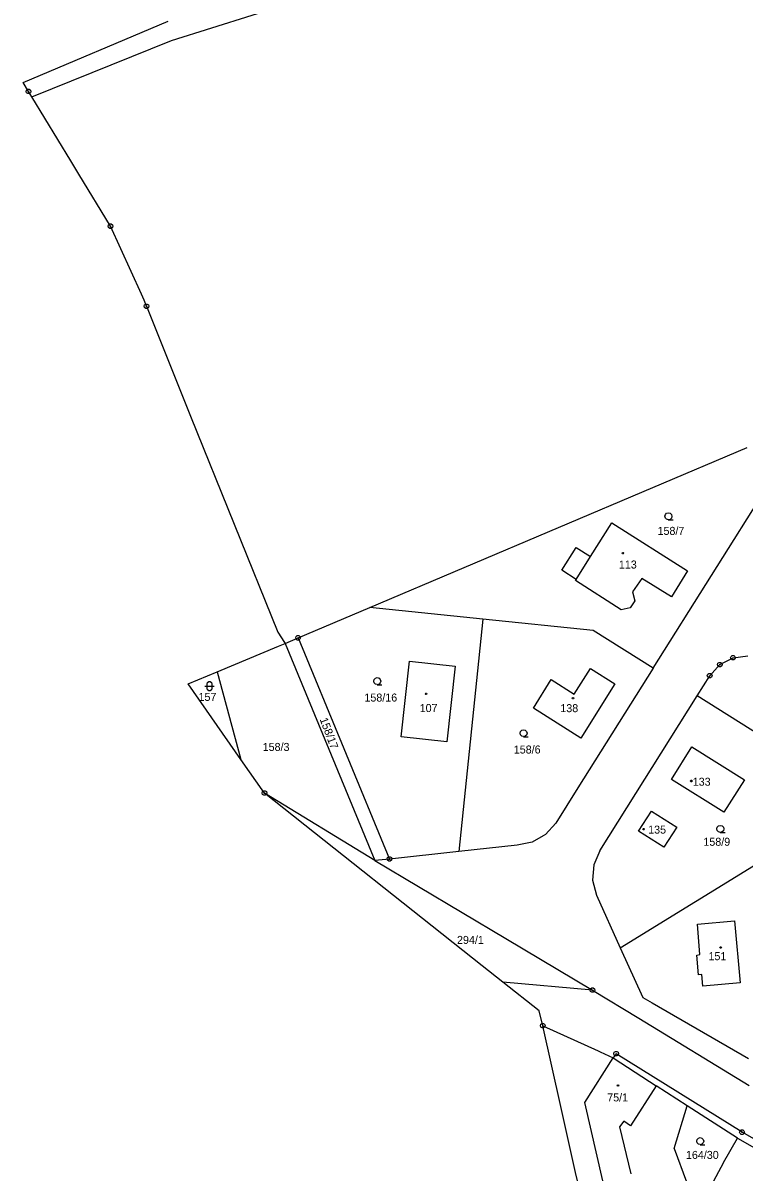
# Model space of a CAD drawing. Extents: x -780000 to -777378, y -1011169 to -1009297.
# Drawn here: x -779564.1 to -779410.9, y -1010124.6 to -1009880.5 of the extents above; entities that cross this region are included whole.
import ezdxf

# ---------------------------------------------------------------- set-up
doc = ezdxf.new("R2010")
doc.units = 0
for name, color, linetype in [('Default', 7, 'Continuous'), ('KN_HRANICE', 7, 'Continuous'), ('KN_KULTURY', 7, 'Continuous'), ('KN_PARCELY', 7, 'Continuous'), ('KN_SLUCKY', 7, 'Continuous')]:
    doc.layers.add(name, color=color, linetype=linetype)

# ---------------------------------------------------------------- blocks, each defined once
blk = doc.blocks.new('304')
at = {"layer": 'Default'}
blk.add_lwpolyline([(0, 0), (-0.38, 0.1), (-0.65, 0.37), (-0.75, 0.74), (-0.65, 1.11), (-0.38, 1.38), (-0.01, 1.48), (0.36, 1.38), (0.63, 1.11), (0.73, 0.73), (0.63, 0.35), (0.36, 0.08), (-0.02, -0.02), (0.98, -0.02)], dxfattribs=at)
blk = doc.blocks.new('316')
at = {"layer": 'Default'}
for points in [[(-1, 1), (0.27, 1), (1, 1)], [(-0.5, 1.5), (-0.4, 1.79), (-0.15, 1.97), (0.16, 1.97), (0.41, 1.79), (0.51, 1.5), (0.51, 0.5), (0.41, 0.21), (0.16, 0.03), (-0.15, 0.03), (-0.4, 0.21), (-0.5, 0.5), (-0.5, 1.5)]]:
    blk.add_lwpolyline(points, dxfattribs=at)
blk = doc.blocks.new('105')
at = {"layer": 'Default'}
blk.add_line((-0.12, 0), (0.12, 0), dxfattribs=at)
blk.add_lwpolyline([(0.15, 0.48), (0.4, 0.3), (0.5, 0.01), (0.4, -0.28), (0.15, -0.46), (-0.16, -0.46), (-0.41, -0.28), (-0.51, 0.01), (-0.41, 0.3), (-0.16, 0.48), (0.15, 0.48)], dxfattribs=at)
blk = doc.blocks.new('402')
at = {"layer": 'Default'}
blk.add_lwpolyline([(0.09, 0.15), (0.18, 0), (0.09, -0.15), (-0.09, -0.15), (-0.18, 0), (-0.09, 0.15), (0.09, 0.15)], dxfattribs=at)

msp = doc.modelspace()

# ---------------------------------------------------------------- linework, layer by layer
at = {"layer": 'KN_HRANICE'}
for p, q in [((-779532.56, -1009884.15), (-779506.87, -1009876.1)), ((-779564.1, -1009893.09), (-779533.32, -1009880.08)), ((-779562.25, -1009896.12), (-779532.56, -1009884.15)), ((-779562.94, -1009894.99), (-779564.1, -1009893.09)), ((-779562.25, -1009896.12), (-779562.94, -1009894.99)), ((-779553.96, -1009909.75), (-779562.25, -1009896.12)), ((-779552.25, -1009912.56), (-779553.96, -1009909.75)), ((-779545.52, -1009923.61), (-779552.25, -1009912.56)), ((-779538.94, -1009938.03), (-779545.52, -1009923.61)), ((-779538.37, -1009939.28), (-779538.94, -1009938.03)), ((-779537.89, -1009940.61), (-779538.37, -1009939.28)), ((-779537.89, -1009940.61), (-779528.57, -1009963.94)), ((-779528.57, -1009963.94), (-779510, -1010009.82)), ((-779490.5, -1010004.56), (-779410.38, -1009970.58)), ((-779430.36, -1010017.45), (-779405.63, -1009978.11)), ((-779443.63, -1009993.74), (-779439.14, -1009986.62)), ((-779439.14, -1009986.62), (-779423.07, -1009996.75)), ((-779449.77, -1009996.67), (-779446.72, -1009991.8)), ((-779446.72, -1009991.8), (-779443.63, -1009993.74)), ((-779446.7, -1009998.61), (-779449.77, -1009996.67)), ((-779423.07, -1009996.75), (-779426.49, -1010002.32)), ((-779446.86, -1009998.86), (-779446.7, -1009998.61)), ((-779437.12, -1010005.06), (-779446.86, -1009998.86)), ((-779432.77, -1009998.38), (-779434.71, -1010001.23)), ((-779426.49, -1010002.32), (-779432.77, -1009998.38)), ((-779434.71, -1010001.23), (-779434.23, -1010003.15)), ((-779434.23, -1010003.15), (-779435.26, -1010004.63)), ((-779505.72, -1010011.01), (-779490.5, -1010004.56)), ((-779466.49, -1010007.04), (-779490.5, -1010004.56)), ((-779435.26, -1010004.63), (-779437.12, -1010005.06)), ((-779466.49, -1010007.04), (-779471.6, -1010056.37)), ((-779443.07, -1010009.46), (-779466.49, -1010007.04)), ((-779510, -1010009.82), (-779508.57, -1010011.97)), ((-779508.48, -1010012.18), (-779505.72, -1010011.01)), ((-779505.72, -1010011.01), (-779486.32, -1010057.97)), ((-779430.36, -1010017.45), (-779443.07, -1010009.46)), ((-779522.9, -1010018.23), (-779509.9, -1010012.78)), ((-779509.9, -1010012.78), (-779508.48, -1010012.18)), ((-779508.57, -1010011.97), (-779508.48, -1010012.18)), ((-779508.48, -1010012.18), (-779489.42, -1010058.31)), ((-779483.83, -1010032.01), (-779482.07, -1010015.94)), ((-779482.07, -1010015.94), (-779472.39, -1010016.99)), ((-779416.21, -1010016.69), (-779413.4, -1010015.24)), ((-779413.4, -1010015.24), (-779410.26, -1010014.85)), ((-779529.07, -1010020.81), (-779522.9, -1010018.23)), ((-779522.9, -1010018.23), (-779517.85, -1010036.84)), ((-779472.39, -1010016.99), (-779474.14, -1010033.11)), ((-779447.1, -1010022.98), (-779443.68, -1010017.51)), ((-779443.68, -1010017.51), (-779438.46, -1010020.79)), ((-779418.36, -1010019.05), (-779416.21, -1010016.69)), ((-779517.85, -1010036.84), (-779529.07, -1010020.81)), ((-779455.79, -1010025.95), (-779452.01, -1010019.89)), ((-779452.01, -1010019.89), (-779447.1, -1010022.98)), ((-779438.46, -1010020.79), (-779445.71, -1010032.28)), ((-779421.04, -1010023.31), (-779418.36, -1010019.05)), ((-779441.71, -1010056.21), (-779421.04, -1010023.31)), ((-779402.59, -1010034.91), (-779421.04, -1010023.31)), ((-779445.71, -1010032.28), (-779455.79, -1010025.95)), ((-779474.14, -1010033.11), (-779483.83, -1010032.01)), ((-779512.85, -1010043.97), (-779517.85, -1010036.84)), ((-779489.42, -1010058.31), (-779512.85, -1010043.97)), ((-779466.67, -1010080.62), (-779512.85, -1010043.97)), ((-779451.04, -1010050.34), (-779453.2, -1010052.79)), ((-779437.34, -1010076.8), (-779393.43, -1010049.78)), ((-779459.24, -1010055.03), (-779471.6, -1010056.37)), ((-779456.04, -1010054.41), (-779459.24, -1010055.03)), ((-779471.6, -1010056.37), (-779486.32, -1010057.97)), ((-779441.71, -1010056.21), (-779442.97, -1010059.22)), ((-779486.32, -1010057.97), (-779489.42, -1010058.31)), ((-779489.42, -1010058.31), (-779461.6, -1010074.87)), ((-779442.97, -1010059.22), (-779443.2, -1010062.48)), ((-779443.2, -1010062.48), (-779442.37, -1010065.63)), ((-779442.37, -1010065.63), (-779437.34, -1010076.8)), ((-779420.98, -1010071.8), (-779413.13, -1010071.11)), ((-779420.44, -1010078.28), (-779420.98, -1010071.8)), ((-779413.13, -1010071.11), (-779411.92, -1010084.25)), ((-779461.6, -1010074.87), (-779443.22, -1010085.81)), ((-779437.34, -1010076.8), (-779432.57, -1010087.39)), ((-779421.12, -1010078.36), (-779420.44, -1010078.28)), ((-779420.75, -1010082.53), (-779421.12, -1010078.36)), ((-779462.29, -1010084.1), (-779466.67, -1010080.62)), ((-779443.22, -1010085.81), (-779462.29, -1010084.1)), ((-779454.55, -1010090.24), (-779462.29, -1010084.1)), ((-779420.01, -1010082.47), (-779420.75, -1010082.53)), ((-779419.8, -1010084.97), (-779420.01, -1010082.47)), ((-779411.92, -1010084.25), (-779419.8, -1010084.97)), ((-779443.22, -1010085.81), (-779433.43, -1010091.77)), ((-779453.79, -1010093.36), (-779454.55, -1010090.24)), ((-779433.43, -1010091.77), (-779409.97, -1010106.05)), ((-779449.96, -1010110.52), (-779453.79, -1010093.36)), ((-779444.86, -1010109.68), (-779438.86, -1010100.16)), ((-779438.86, -1010100.16), (-779431.13, -1010105.19)), ((-779431.13, -1010105.19), (-779429.69, -1010106.11)), ((-779423.11, -1010110.38), (-779429.69, -1010106.11)), ((-779446.83, -1010124.56), (-779449.96, -1010110.52)), ((-779441.05, -1010126.3), (-779444.86, -1010109.68)), ((-779425.9, -1010119.46), (-779423.11, -1010110.38)), ((-779412.49, -1010117.26), (-779423.11, -1010110.38)), ((-779415.42, -1010122.39), (-779412.49, -1010117.26)), ((-779412.49, -1010117.26), (-779403.77, -1010122.18)), ((-779425.9, -1010119.46), (-779423.3, -1010126.5)), ((-779415.42, -1010122.39), (-779419.17, -1010129.45)), ((-779439.02, -1010157.72), (-779446.83, -1010124.56))]:
    msp.add_line(p, q, dxfattribs=at)
for points in [[(-779430.36, -1010017.45), (-779446.32, -1010042.84), (-779451.04, -1010050.34)], [(-779453.2, -1010052.79), (-779453.68, -1010053.07), (-779456.04, -1010054.41)], [(-779432.57, -1010087.39), (-779430.6, -1010088.52), (-779410.1, -1010100.31)], [(-779453.79, -1010093.36), (-779442.04, -1010098.71), (-779441.59, -1010098.92), (-779438.86, -1010100.16)]]:
    msp.add_lwpolyline(points, dxfattribs=at)
for points in [[(-779426.49, -1010041.07), (-779422.15, -1010034.15), (-779410.97, -1010041.14), (-779415.34, -1010048.05)], [(-779433.48, -1010052.09), (-779430.71, -1010047.79), (-779425.37, -1010051.19), (-779428.1, -1010055.49)]]:
    msp.add_lwpolyline(points, close=True, dxfattribs=at)
at = {"layer": 'KN_SLUCKY'}
for p, q in [((-779446.7, -1009998.61), (-779443.63, -1009993.74)), ((-779438.22, -1010099.31), (-779438.86, -1010100.16)), ((-779411.49, -1010115.98), (-779438.22, -1010099.31)), ((-779429.69, -1010106.11), (-779435.16, -1010114.65)), ((-779436.55, -1010113.62), (-779437.52, -1010114.87)), ((-779435.16, -1010114.65), (-779436.55, -1010113.62)), ((-779437.52, -1010114.87), (-779435.11, -1010124.84)), ((-779379.59, -1010134.15), (-779411.49, -1010115.98))]:
    msp.add_line(p, q, dxfattribs=at)

# ---------------------------------------------------------------- block references
at = {"layer": 'KN_KULTURY'}
for name, p in [('304', (-779427.12, -1009985.94)), ('402', (-779436.78, -1009993.04)), ('316', (-779524.53, -1010022.26)), ('304', (-779488.9, -1010020.94)), ('402', (-779478.55, -1010022.91)), ('402', (-779447.37, -1010023.8)), ('304', (-779457.85, -1010031.99)), ('402', (-779422.27, -1010041.41)), ('402', (-779432.4, -1010051.64)), ('304', (-779416.09, -1010052.31)), ('402', (-779416.04, -1010076.77)), ('402', (-779437.84, -1010106.08)), ('304', (-779420.36, -1010118.61))]:
    msp.add_blockref(name, p, dxfattribs=at)
at = {"layer": 'KN_PARCELY'}
for p in [(-779562.94, -1009894.99), (-779545.52, -1009923.61), (-779537.89, -1009940.61), (-779505.72, -1010011.01), (-779416.21, -1010016.69), (-779413.4, -1010015.24), (-779418.36, -1010019.05), (-779512.85, -1010043.97), (-779486.32, -1010057.97), (-779443.22, -1010085.81), (-779453.79, -1010093.36), (-779438.22, -1010099.31), (-779411.49, -1010115.98)]:
    msp.add_blockref('105', p, dxfattribs=at)

# ---------------------------------------------------------------- texts
for s, p in [('158/7', (-779429.43, -1009989.15)), ('113', (-779437.64, -1009996.29)), ('157', (-779526.85, -1010024.4)), ('158/16', (-779491.64, -1010024.54)), ('138', (-779450.06, -1010026.79)), ('158/3', (-779513.23, -1010035.02)), ('158/6', (-779459.94, -1010035.57)), ('133', (-779421.96, -1010042.41)), ('135', (-779431.42, -1010052.58)), ('158/9', (-779419.7, -1010055.16)), ('294/1', (-779471.99, -1010076)), ('151', (-779418.62, -1010079.45)), ('75/1', (-779440.11, -1010109.44)), ('164/30', (-779423.4, -1010121.65))]:
    msp.add_text(s, height=1.7, dxfattribs=at).set_placement(p)
for s, rotation, p in [('107', 0.802, (-779479.9, -1010026.79)), ('158/17', 290.661, (-779501.16, -1010028.3))]:
    msp.add_text(s, height=1.7, rotation=rotation, dxfattribs=at).set_placement(p)

doc.saveas('drawing.dxf')
